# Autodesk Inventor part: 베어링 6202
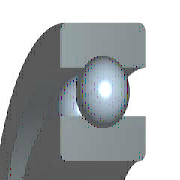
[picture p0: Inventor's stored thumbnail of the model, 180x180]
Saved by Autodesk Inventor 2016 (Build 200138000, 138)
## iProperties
IsCustomPart: 1
Created: 2015-12
Part Number: 베어링 6202
Material: 강철, 연강
Description: 깊은 그루브 볼 베어링
Document SubType Name: Modeling
Standard: KS B 2023
Designer: mdu
Standards Organization: KS
Language: ko-KR
Size Designation: 6202 - 15 x 35 x 11
Categories: <MemberInstance><Categories><Category DisplayName="샤프트 부품" InternalName="7f7aeb1f-a693-4053-b835-cee3144e0d98" Mnemonic="SHFT"><Category DisplayName="베어링" Inter
Density: 7.86 g/cm^3
Mass: 45.8725 g
Surface Area: 51.5584 cm^2
Volume: 5.83619 cm^3
Appearance: 노란색
Author: mdu
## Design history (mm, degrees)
sketch "스케치" dims "d0" = 5.2 (= -0.26 x WD + 0.26 x BD)
  geometry: L1 (2.9, 12.5)-(8.1, 12.5); L2 (5.5, 12.5)-(5.5, 9.9); L3 (5.5, 12.5)-(5.5, 15.1); L4 (3.568, 10.76)-(0, 10.76); L5 (0, 7.5)-(11, 7.5); L6 (3.568, 14.24)-(0, 14.24); L7 (0, 17.5)-(11, 17.5); L8 (11, 7.5)-(11, 10.76); L9 (7.432, 10.76)-(11, 10.76); L10 (7.432, 14.24)-(11, 14.24); L11 (11, 17.5)-(11, 14.24); L12 (-1.4, 0)-(8.4, 0) reference; L13 (0, -0.3)-(0, 5.3) reference
  constraints: 22 end point, 4 point on line, 2 collinear, 2 perpendicular, 2 symmetric about line, 1 midpoint, 1 parallel, 14 other
  dimensions: "d9" = 15 diameter of L5 L12 (= WD); "d11" = 35 diameter of L7 L12 (= BD); "d12" = 11 distance between parallel lines of L8 L13 (= KB); "d13" = 21.52 diameter of L9 L12 (= 0.326 x BD + 0.674 x WD)
revolve "본체" stored, may be unused: angle "d6" = 90 deg
revolve "볼" stored, may be unused: angle "d7" = 90 deg
pattern_circular "IDS_ARRAYBALL[SIMPL:T]" dims angle "d3" = 360 deg
body "Solid1"
fillet "모깎기1" dims "d1" = 0.6 (= KRS)
other parameters: "WD" = 15 [user parameter; used in 5 equation terms], "BD" = 35 [user parameter; used in 5 equation terms], "KB" = 11 [user parameter; used in 1 equation term], "KRS" = 0.6 [user parameter; used in 1 equation term], "d4" = 0, "d5" = 0, "d8" = 0, "d14" = 0, "d15" = 0, "BBA" = 0 [user parameter], "BC0" = 3750000 [user parameter], "BC" = 7800000 [user parameter], "BR" = 17.5 (= 0.5 x BD) [user parameter], "WR" = 7.5 (= 0.5 x WD) [user parameter]
